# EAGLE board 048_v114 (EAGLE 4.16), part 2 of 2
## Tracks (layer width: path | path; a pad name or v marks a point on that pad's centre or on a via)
+3V3  (via drill 0.25)
  Top 0.15: IC3.10 7.28,33.38 7.28,33.78 IC3.11 7.48,34.18 v8.08,34.13 | v10.03,35.63 10.03,36.03 C4.1 9.68,37.08 9.43,37.63 6.38,37.63 6.03,37.93 6.03,38.68 4.08,40.48 | 4.08,40.48 4.08,38.48 R2.2 | 4.08,40.48 4.08,44.23 10.18,50.28 10.18,50.88 IC13.6 | T1.2 18.88,29.78 | 19.68,30.08 R18.2 20.33,30.18 20.38,30.08 | IC9.P$3 16.03,17.88 | 18.08,29.28 T1.2 | 26.98,37.28 IC8.6 27.98,36.98 | 26.98,38.08 IC8.5 | 33.08,37.08 IC8.3 35.28,36.88 35.28,36.68 | 27.88,29.48 27.88,29.38 IC7.8 | 27.88,30.18 IC7.7 28.93,30.58 | 35.08,31.48 C33.1 35.68,31.58 | 34.08,31.48 IC7.3 31.83,31.48 | v37.63,33.78 37.48,33.98 | T1.2 18.08,29.58 | IC14.36 54.88,10.83 54.88,11.88 55.23,12.13 63.03,12.13 63.38,11.68 IC12.1 63.88,10.58 64.23,10.23 65.03,10.23 65.28,10.58 IC12.3 65.78,11.68 v65.78,12.53 | 61.83,24.93 61.68,24.78 61.03,24.73 IC1.26 | 61.83,24.93 64.28,27.38 64.28,27.78 63.28,28.78 62.88,28.78 T2.2 62.08,29.48 61.78,29.48 60.78,30.48 v60.78,33.53 | 55.78,19.38 57.58,21.18 59.68,21.18 IC1.19 61.08,21.18 61.88,21.18 62.28,21.58 64.33,21.58 64.63,21.28 64.78,21.28 X7.1 | 55.78,19.38 55.33,18.98 55.28,18.73 IC1.10 | 55.78,19.38 52.28,22.93 50.43,22.93 49.78,23.63 49.38,23.63 IC1.57 48.03,23.58 v44.63,23.58 | v61.88,24.78 61.88,24.88 61.83,24.93 | v56.38,33.53 56.33,32.48 55.78,31.98 IC1.38 | C2.1 60.48,47.08 60.08,47.08 C25.1 59.18,47.58 58.58,47.58 | R9.2 53.88,48.88 53.48,48.88 51.88,47.53 51.88,46.58 IC6.32 51.88,45.68 51.83,44.38 54.88,41.28 | 58.58,47.58 55.98,47.58 54.68,48.88 R9.2 | 58.58,47.58 v58.58,46.93 | C1.2 58.68,36.88 59.18,36.88 C26.1 60.08,36.78 60.38,36.78 C27.1 | 54.88,41.28 55.48,41.88 56.68,41.88 IC6.19
  Top 0.15: 54.88,41.28 54.73,41.13 | 54.73,41.13 52.38,38.78 52.38,37.58 IC6.6 | 56.38,39.43 56.68,39.43 IC6.14 | 54.73,41.13 56.38,39.43 | 56.38,39.43 56.08,39.23 56.08,38.63 56.33,38.43 57.18,38.43 57.38,38.23 57.38,37.58 57.68,37.28 58.08,37.28 C1.2 | v58.48,35.88 58.48,36.48 C1.2 | IC6.45 48.58,40.38 48.73,40.48 48.98,40.68 48.98,41.18 48.68,41.38 IC6.43 47.68,41.43 46.28,41.43 45.88,41.78 45.83,43.03 45.88,43.73 46.18,43.93 47.68,43.93 IC6.38 | 39.08,47.68 IC10.3 | 38.98,49.28 IC10.1 | X3.5 46.38,53.38 46.93,52.68 48.93,52.68 49.18,52.43 51.58,52.43 52.53,53.38 X2.1 | 42.93,48.03 v43.13,48.28 | 53.88,49.48 R9.2
  Top 0.305: 18.88,29.78 19.48,29.88 19.68,30.08 | 16.03,17.88 17.63,19.48 17.63,28.93 18.08,29.28 | 26.98,37.28 26.98,38.08 | 32.58,36.98 27.98,36.98 | 33.08,37.08 32.58,36.98 | 27.88,30.18 27.88,29.48 20.98,29.48 20.78,29.58 20.38,30.08 | 34.08,31.48 35.08,31.48 | 35.68,31.58 v37.63,33.78 | 28.93,30.58 31.08,30.58 31.83,31.48 | 35.28,36.68 37.48,34.28 37.48,33.98 | 18.08,29.58 v16.53,29.58 | 39.58,48.28 39.08,47.68 | 39.58,48.28 39.53,48.98 38.98,49.28 | v43.13,48.28 39.58,48.28 | 45.83,43.03 36.53,43.03 36.48,43.18 | 36.48,43.18 36.13,43.58 36.13,44.18 36.53,44.58 39.73,44.58 42.93,48.03 | v52.88,50.48 53.88,49.48 | 32.58,36.98 32.58,38.98 v33.63,39.78 | v36.48,42.68 36.48,43.18
  Bottom 0.15: v10.03,35.63 8.98,34.13 v8.08,34.13 8.08,33.93 7.78,33.63 7.78,32.18 10.43,29.53 v16.53,29.58 | v37.63,33.78 41.28,33.78 U$1.31 | 42.78,23.68 42.78,25.58 42.28,25.88 U$1.15 | 42.78,23.68 42.78,22.58 42.38,22.38 42.28,22.38 U$1.8 | v44.63,23.58 42.78,23.68 | v61.88,24.78 64.98,21.68 X7.1 65.63,21.13 66.08,20.63 66.08,16.93 65.78,16.68 v65.78,12.53 | 58.93,35.43 59.08,35.58 C31.+ 60.78,34.78 v60.78,33.53 | 58.93,35.43 58.33,35.43 57.83,34.93 v56.38,33.53 | v58.58,46.93 59.08,47.08 C30.+ | v58.48,35.88 58.93,35.43 | 42.38,49.68 42.28,49.68 D1.A 42.28,48.08 | 52.28,51.08 53.08,51.88 53.08,53.28 X2.1
  Bottom 0.305: 42.38,49.68 43.03,50.48 51.53,50.48 52.28,51.08 v52.88,50.48 | v43.13,48.28 42.28,48.08 | v33.63,39.78 v36.48,42.68
+5V  (via drill 0.25)
  Top 0.15: 27.38,7.38 IC5.2 27.28,6.98 | 27.68,7.38 IC5.3 27.78,6.98 | 27.03,6.63 27.18,6.78 | 22.48,6.98 LED1.A 21.48,8.08 | v40.93,8.28 40.73,8.38 41.33,8.98 41.73,8.98 42.08,9.33 42.78,10.08 43.18,10.08 IC2.20 | 21.48,9.08 D4.A 20.38,9.08
  Top 0.305: 27.18,6.78 27.28,6.98 | 22.73,6.63 27.03,6.63 | 27.78,6.98 v27.73,6.08
  Top 0.406: 27.38,7.38 27.68,7.38 | 22.48,6.98 22.73,6.63 | 21.48,9.08 21.48,8.08 | v19.28,8.08 20.38,9.08
  Bottom 0.15: 14.28,8.08 L1.2 16.28,8.08 | v40.93,8.28 34.98,8.28 32.58,5.88 28.23,5.88 28.13,5.98 v27.73,6.08
  Bottom 0.305: 14.28,8.08 14.28,9.38 14,9.66 C36.1 13.94,10.29 14.88,11.23 14.84,11.28 C37.+
  Bottom 0.406: 16.28,8.08 v19.28,8.08
+BAT  (via drill 0.25)
  Top 0.15: R3.2 13.18,5.08 13.18,7.08 12.03,8.03 12.03,10.48 14.58,12.98 C17.2 15.28,13.88 | 15.28,16.08 IC9.P$4 | v31.43,46.88 31.48,47.38 IC11.2 | v32.13,51.83 32.38,51.43 | 32.48,51.18 32.48,50.98 IC11.7 | IC5.8 27.68,10.28 27.38,10.28 IC5.9 27.28,10.58 v27.28,11.18 | v7.08,18.18 3.48,21.78 IC4.14
  Top 0.305: 32.38,51.43 32.48,51.18
  Top 0.406: 15.28,13.88 v15.28,15.03 15.28,16.08
  Bottom 0.15: 29.98,8.08 C9.+ | 17.13,3.93 R13.1 | v7.08,18.18 11.78,18.18 11.83,18.03 11.88,18.08 | 31.28,46.78 v31.43,46.88 | v15.28,15.03 15.18,14.78 15.13,14.98
  Bottom 0.305: v31.43,46.88 31.48,50.78 v32.13,51.83 | v27.28,11.18 27.28,10.78 29.38,8.68 | 29.38,8.68 29.98,8.08 | 20.23,3.93 22.18,3.93 22.58,3.38 23.98,3.38 29.38,8.68 | 20.23,3.93 17.13,3.93 | 11.83,18.03 15.13,14.98 19.43,14.98 20.23,14.18 20.23,3.93 | 31.28,46.78 30.93,46.78 30.18,45.78 29.83,45.78 29.58,46.03 27.93,46.03 17.18,35.28 17.18,28.88 11.88,23.68 11.88,18.08
AGND  (via drill 0.25)
  Top 0.15: C2.2 60.48,48.78 60.08,48.78 C25.2 59.18,49.28 v58.63,49.88 | C24.1 40.78,40.68 40.78,39.58 R12.2 | 48.98,42.18 48.73,42.43 IC6.41 48.18,42.48 48.18,42.88 IC6.40 | 48.98,42.18 49.38,41.83 49.38,39.78 48.83,39.38 48.58,39.38 IC6.47 47.68,39.38 46.13,39.38 45.63,39.98 41.93,39.98 41.23,40.68 41.28,40.68 C24.1 | 48.98,42.18 49.08,42.28 49.08,44.18 48.68,44.38 48.58,44.38 IC6.37 48.58,44.48 v48.58,44.98 | 9.48,51.58 IC13.5 9.28,50.88 9.28,50.08 3.38,44.18 3.38,43.48 R25**.2 | 9.48,53.28 IC13.2 9.48,54.08 10.03,54.53 14.13,54.53 16.98,51.38 16.98,49.93 16.83,49.78 16.83,48.18 C44.1 16.38,47.28 16.38,46.48 C40.1 16.38,45.58 16.38,44.68 C41.1 | v55.73,20.33 56.18,20.48 56.33,20.63 57.28,21.63 59.73,21.63 IC1.20 | v35.28,7.08 35.28,8.38 34.03,9.48 34.03,11.38 32.28,12.88 31.28,13.83 v27.78,13.83 | v18.18,34.58 15.98,36.78 15.98,38.03 15.58,38.38 C23.1 15.58,39.28 15.58,39.48 15.93,39.73 15.93,41.43 15.58,41.78 C22.2 14.68,42.58 15.88,43.78 C41.1 | C24.1 40.28,40.98 19.68,40.98 16.88,43.78 C41.1
  Top 0.305: 9.48,53.28 9.48,51.58
  Bottom 0.15: C30.- 59.08,49.88 v58.63,49.88 58.38,49.78 57.33,49.78 54.23,46.18 49.83,46.18 v48.58,44.98 | v55.73,20.33 55.73,20.18 52.28,16.73 52.28,11.88 50.83,10.43 46.83,10.43 43.48,7.08 v35.28,7.08 | v27.78,13.83 24.93,17.28 23.13,17.28 22.13,18.48 22.13,24.13 23.33,25.08 25.13,25.08 25.63,25.53 25.63,26.53 24.63,27.53 22.33,27.53 21.08,28.73 19.08,28.73 18.18,29.58 v18.18,34.58
BT_RES  (via drill 0.25)
  Top 0.15: v51.73,6.03 53.38,6.03 IC14.43 | v57.38,16.88 IC1.14
  Bottom 0.15: v51.73,6.03 52.08,6.38 52.08,8.63 54.73,11.23 54.73,15.78 55.78,16.88 v57.38,16.88
BUSA0  (via drill 0.25)
  Top 0.15: v34.33,16.93 35.88,15.48 IC2.1 | v50.88,28.33 51.33,28.33 51.78,28.98 IC1.46
  Bottom 0.15: v34.33,16.93 34.33,20.73 U$3.1 33.33,22.58 33.33,24.03 39.08,29.78 41.28,29.78 U$1.23 42.28,29.88 42.43,29.78 48.53,29.78 49.98,28.33 v50.88,28.33
BUSA1  (via drill 0.25)
  Top 0.15: v46.53,27.93 47.88,27.93 IC1.49 | v34.78,12.78 35.88,12.78 IC2.5 | v30.08,20.08 v34.13,23.83
  Bottom 0.15: v46.53,27.93 45.38,29.28 42.28,29.28 U$1.22 41.28,29.28 39.28,29.28 34.13,24.13 v34.13,23.83 | 28.88,18.93 27.33,20.58 U$3.3 | 28.88,18.93 32.28,15.13 32.73,14.68 32.73,13.98 33.93,12.78 v34.78,12.78 | 28.88,18.93 v30.08,20.08
BUSA2  (via drill 0.25)
  Top 0.15: v44.88,28.63 46.28,27.23 48.03,27.23 IC1.50 | v34.78,15.23 35.53,14.08 IC2.3
  Bottom 0.15: v44.88,28.63 44.63,28.63 44.48,28.78 42.28,28.78 U$1.21 41.28,28.78 39.63,28.78 34.98,24.18 34.98,15.33 | 34.98,15.33 v34.78,15.23 | 34.98,15.33 32.73,17.53 32.73,28.68 31.53,30.13 31.53,31.23 U$3.5
BUSA3  (via drill 0.25)
  Top 0.15: v45.03,27.58 45.23,27.38 45.98,26.78 47.53,26.78 47.58,26.73 47.98,26.73 IC1.51 | v35.18,9.58 35.78,8.98 35.88,8.98 IC2.11
  Bottom 0.15: v45.03,27.58 44.33,28.28 42.28,28.28 U$1.20 41.28,28.28 39.93,28.28 37.48,25.93 35.43,23.88 35.43,13.88 35.13,13.43 | v35.18,9.58 35.18,11.78 35.38,11.98 35.38,13.08 35.13,13.43 | 35.13,13.43 34.63,13.43 34.38,13.68 30.68,17.68 30.68,20.68 U$3.2
BUSA4  (via drill 0.25)
  Top 0.15: v47.08,26.23 47.88,26.18 IC1.52 | v37.58,16.93 37.58,15.08 37.43,14.78 37.23,14.78 IC2.2 | v39.48,26.78 v37.23,28.98
  Bottom 0.15: v47.08,26.23 45.43,26.23 44.58,27.08 43.93,27.78 42.28,27.78 U$1.19 41.28,27.78 40.58,27.78 39.58,26.88 | v37.58,16.93 37.58,18.03 36.78,18.83 36.78,22.68 39.23,25.08 39.23,26.48 39.58,26.88 | v37.23,28.98 34.38,31.88 U$3.6 | 39.58,26.88 v39.48,26.78
BUSA5  (via drill 0.25)
  Top 0.15: v43.83,26.88 44.68,26.03 46.28,26.03 46.63,25.68 48.08,25.68 IC1.53 | v37.78,10.18 37.18,10.18 IC2.9 | v38.48,25.98 39.53,25.98 v39.98,26.08
  Bottom 0.15: v43.83,26.88 43.33,27.18 43.23,27.28 42.28,27.28 U$1.18 41.28,27.28 41.08,27.28 v39.98,26.08 | v37.78,10.18 37.78,10.58 35.88,12.48 35.88,23.58 38.28,25.98 v38.48,25.98
BUSA6  (via drill 0.25)
  Top 0.15: v46.13,25.33 46.38,25.33 46.53,25.18 48.08,25.18 IC1.54 | v39.68,11.28 38.43,9.48 37.23,9.48 IC2.10
  Bottom 0.15: U$1.17 42.28,26.78 43.03,26.78 44.48,25.33 v46.13,25.33 46.48,24.18 44.48,22.08 44.48,17.58 39.68,12.78 v39.68,11.28
BUSA7  (via drill 0.25)
  Top 0.15: v45.38,24.68 48.08,24.68 IC1.55 | v39.18,16.93 39.18,13.13 38.28,12.28 37.18,12.28 IC2.6
  Bottom 0.15: v45.38,24.68 44.38,24.68 42.78,26.28 42.28,26.28 U$1.16 41.28,26.28 41.08,26.28 37.18,22.38 37.18,19.43 39.18,17.43 v39.18,16.93
EN_LOAD  (via drill 0.25)
  Top 0.15: v26.68,11.83 26.68,10.58 IC5.10 | v32.08,8.68 32.48,8.58 33.03,8.58 34.03,7.48 34.08,7.43 34.08,6.13 34.63,5.58 37.38,5.58 v37.73,5.78 | v53.73,15.38 53.73,16.53 54.28,17.08 IC1.8
  Bottom 0.15: v26.68,11.83 27.53,11.83 27.98,11.33 27.98,10.78 30.13,8.63 31.73,8.63 31.78,8.68 v32.08,8.68 | v37.73,5.78 43.68,5.78 45.68,7.78 50.03,7.78 53.73,11.48 v53.73,15.38
EN_REG  (via drill 0.25)
  Top 0.15: R19.1 26.38,4.68 24.98,4.68 D3.C 23.68,4.73 22.43,4.73 21.93,3.98 20.08,3.98 15.93,8.18 15.93,10.23 17.03,11.28 23.78,11.28 | v16.83,20.58 15.98,20.58 IC9.P$1 | 23.78,11.28 23.78,10.78 D4.C | 23.78,11.28 v23.78,13.83
  Bottom 0.15: v23.78,13.83 v16.83,20.58
ENTPS  (via drill 0.25)
  Top 0.15: v33.78,51.58 33.08,50.98 IC11.6 | v36.63,51.58 37.13,51.58 38.58,50.13 42.03,50.13 42.23,49.88 v43.38,49.78 | v48.48,32.93 50.23,31.23 50.23,29.13 50.28,29.08 50.28,28.03 50.63,27.68 51.48,27.68 52.18,28.58 52.28,28.98 IC1.45
  Bottom 0.15: v36.63,51.58 v33.78,51.58 | v43.38,49.78 43.58,49.78 43.68,49.88 44.53,49.88 44.78,49.68 44.78,42.38 44.58,42.18 44.58,36.48 45.38,35.73 45.73,35.73 46.08,35.38 46.08,33.83 46.98,32.93 v48.48,32.93
FLASH  (via drill 0.25)
  Top 0.15: v55.38,13.43 54.63,13.43 54.08,13.03 v50.68,13.03 | v47.53,13.28 47.28,13.28 43.58,16.98 v41.48,16.98 | v39.73,19.83 39.48,19.93 38.73,20.53 38.73,23.93 40.58,25.78 40.58,32.68 35.18,38.08 IC8.4 | v55.78,15.13 IC1.11
  Bottom 0.15: v55.78,15.13 55.78,13.98 v55.38,13.43 | v50.68,13.03 48.13,13.03 v47.53,13.28 | v39.73,19.83 v41.48,16.98
FRAM  (via drill 0.25)
  Top 0.15: v57.43,20.13 57.73,20.13 57.93,19.93 59.58,19.93 59.68,20.03 59.68,20.08 IC1.17 | v34.73,6.43 34.73,6.63 34.58,6.78 34.58,7.73 33.48,8.83 33.48,10.93 32.78,11.58 32.63,11.68 30.18,11.68 v29.98,11.93 | v30.23,16.58 v31.28,18.03 | v31.28,23.88 31.28,28.13 31.98,28.88 IC7.1
  Bottom 0.15: v57.43,20.13 53.13,15.88 53.13,11.53 50.03,8.43 45.58,8.43 43.58,6.43 v34.73,6.43 | v29.98,11.93 29.98,13.58 30.23,13.83 v30.23,16.58 | v31.28,18.03 v31.28,23.88
FTPWEN  (via drill 0.25)
  Top 0.15: v40.68,10.58 38.38,8.28 36.98,8.28 IC2.12 | v46.98,21.53 47.28,21.53 47.68,21.68 IC1.61
  Bottom 0.15: v40.68,10.58 46.13,15.98 46.48,15.98 46.98,16.48 v46.98,21.53
FTRD  (via drill 0.25)
  Top 0.15: v41.83,10.83 38.68,7.68 37.18,7.68 IC2.13 | v47.28,22.73 47.68,23.13 IC1.58
  Bottom 0.15: v41.83,10.83 47.83,16.58 47.83,22.03 47.48,22.38 v47.28,22.73
FTRXF
  Top 0.15: IC2.23 44.48,12.28 47.48,12.28 49.03,13.83 49.08,13.93 49.08,15.03 49.58,15.68 50.08,15.68 50.53,16.08 51.28,16.93 IC1.2
FTTXE
  Top 0.15: IC2.22 44.48,11.58 47.38,11.58 49.53,13.73 49.53,14.73 49.93,15.18 50.33,15.18 51.28,16.13 51.78,16.68 IC1.3
FTWR  (via drill 0.25)
  Top 0.15: v41.58,9.68 41.38,9.68 38.78,7.08 37.18,7.08 IC2.14 | v50.03,22.18 49.48,22.68 IC1.59
  Bottom 0.15: v41.58,9.68 41.98,10.03 42.33,10.33 42.43,10.33 49.48,17.38 49.48,21.68 v50.03,22.18
GND  (via drill 0.25)
  Top 0.15: C1.1 58.68,38.18 59.18,38.18 C26.2 | 58.68,39.38 59.18,38.88 C26.2 | 58.68,39.38 57.68,40.38 57.58,40.38 IC6.16 | C26.2 60.08,38.48 60.38,38.48 C27.2 60.88,38.98 60.88,40.68 C28.1 | v58.48,39.18 58.68,39.38 | C12.1 65.18,46.78 65.18,46.28 C13.1 64.88,45.48 64.08,45.48 62.33,43.73 61.53,43.73 60.98,43.18 C3.1 60.48,42.28 60.48,41.58 C28.1 | IC6.20 57.18,42.48 57.18,42.88 IC6.21 | IC6.22 57.18,43.38 57.18,42.98 IC6.21 | IC6.21 57.58,42.88 58.78,42.88 60.08,41.58 C28.1 | C11.1 65.58,35.48 C10.1 65.28,34.18 63.98,34.18 63.08,33.28 63.08,32.38 64.68,30.78 65.08,30.78 66.13,29.93 66.13,26.48 65.48,25.93 X1.3 64.78,25.48 63.58,24.28 61.13,24.23 IC1.25 | C8.1 54.78,14.68 IC1.9 | C45.2 64.38,14.88 64.38,11.68 IC12.2 | X7.3 64.93,18.53 64.33,18.18 64.33,15.68 C45.2 | C8.1 55.38,14.38 62.98,14.38 63.68,15.08 C45.2 | C35.2 33.98,14.13 34.03,12.43 35.03,11.38 35.88,11.58 IC2.7 37.18,11.48 v37.98,11.58 38.98,11.63 39.23,12.08 42.68,12.08 | IC2.26 43.88,13.98 43.88,13.58 IC2.25 43.18,13.28 43.08,13.28 42.63,13.03 42.68,12.08 | C34.1 45.58,8.98 44.48,8.98 IC2.18 | C34.1 46.08,9.28 44.68,10.68 44.48,10.68 IC2.21 43.18,10.88 42.68,11.13 42.68,12.08 | Q4.P$4 46.78,3.18 45.98,2.38 C47.2 45.38,2.18 v44.68,2.18 | Q4.P$4 48.08,3.28 50.38,0.98 Q4.P$2 51.88,0.68 52.48,0.68 C46.2 52.98,0.33 54.08,0.33 54.98,1.63 IC14.1 55.08,3.18 55.33,3.73 55.38,3.78 IC14.49 59.08,3.78 59.08,3.18 IC14.9 | IC14.9 59.08,2.38 59.48,2.38 IC14.10 | IC14.3 56.08,2.38 56.48,2.38 IC14.4 56.58,2.38 56.98,2.38 IC14.5 57.08,2.38 57.48,2.38 IC14.6 57.58,2.38 57.98,2.38 IC14.7 58.08,2.38 58.48,2.38 IC14.8 58.58,2.38 58.98,2.38 IC14.9
  Top 0.15: C34.1 46.18,8.48 46.28,8.48 46.58,8.18 46.58,3.88 Q4.P$4 | C8.1 54.58,14.08 54.08,13.58 50.18,13.58 46.18,9.28 C34.1 | -BAT.1 9.18,2.98 9.18,4.48 R7.1 9.53,5.08 9.53,9.48 8.88,10.03 U$2.P$5 8.58,10.98 8.58,15.58 IC4.5 8.58,17.58 10.58,19.58 | C14.1 12.18,32.48 11.68,32.48 C15.1 11.03,32.63 11.03,34.98 | 11.03,34.98 11.03,37.58 10.58,37.78 C4.2 | C39.2 1.18,21.88 L5.2 1.78,26.08 3.93,23.93 | 3.93,23.93 4.18,23.68 IC4.13 | 5.53,24.28 4.28,24.28 3.93,23.93 | 5.53,24.28 6.63,24.28 6.83,23.68 6.78,23.68 IC4.11 7.28,21.78 7.63,21.23 8.83,21.23 9.28,21.78 IC4.9 9.88,21.78 10.58,21.08 10.58,19.58 | 10.58,19.58 10.58,17.58 IC4.7 | 5.53,24.28 5.48,30.88 IC3.3 5.48,31.38 5.48,31.78 IC3.21 6.48,33.38 6.48,33.68 IC3.12 6.53,34.53 7.33,35.33 8.13,35.33 8.48,35.68 9.03,35.68 9.63,34.98 11.03,34.98 | IC10.2 37.88,48.78 36.98,48.78 C48.2 36.38,49.38 34.98,50.78 R29.1 | IC11.P$1 32.48,48.68 32.48,48.08 IC11.4 32.48,47.38 33.48,46.38 33.48,46.08 C50.1 | IC11.8 31.98,50.28 31.98,49.78 IC11.P$1 | R29.1 34.38,50.48 33.68,49.78 IC11.P$1 | R29.1 35.18,51.28 35.98,52.18 41.93,52.13 43.18,53.38 X3.3 43.73,53.98 44.13,54.53 50.38,54.53 50.68,54.38 50.68,53.53 50.93,53.28 v51.33,53.08 | 53.13,51.53 51.08,49.48 R8.2 50.38,48.88 50.38,46.58 IC6.35 50.38,45.68 50.38,44.53 50.83,44.08 50.83,42.68 51.28,42.23 51.28,38.58 50.98,38.18 | 53.13,51.53 54.98,53.38 X2.3 | 50.98,38.18 42.88,38.18 R12.1 42.08,38.18 42.08,36.68 42.83,36.13 v42.83,35.23 | 50.98,38.18 51.38,37.78 51.38,37.58 IC6.4 51.38,36.33 50.93,35.88 50.93,34.43 R5.2 51.28,34.38 54.28,31.08 IC1.41 | 53.13,51.53 v52.38,52.13
  Top 0.15: 25.88,31.08 25.23,31.78 25.23,34.93 25.88,35.43 25.88,35.48 IC8.7 | 25.88,31.08 30.38,31.08 31.98,32.68 IC7.4 34.08,32.78 35.08,32.78 C33.2 35.68,32.78 v36.18,33.28 | IC5.4 28.28,6.98 28.28,4.98 R19.2 28.48,4.53 30.23,4.53 30.63,5.18 30.48,7.28 C16.2 31.38,7.28 32.78,7.28 v32.98,7.43 | v20.03,29.43 20.03,28.98 C32.2 | v28.28,12.08 28.28,10.58 IC5.7 | v22.78,19.58 22.18,19.58 IC9.P$5 20.78,17.38 17.28,13.88 C17.1 16.68,12.98 v16.68,12.43 | v25.58,30.23 25.88,31.08
  Bottom 0.15: v58.48,39.18 59.08,39.18 C31.- 61.43,38.68 64.58,38.68 65.08,38.18 64.98,29.48 63.18,28.08 | 62.93,27.88 63.18,28.08 | 62.93,27.88 62.93,27.48 64.53,25.88 X1.3 | v44.68,2.18 44.68,1.68 ANT2.P$3 | 62.93,27.88 62.83,27.88 62.03,28.83 61.38,28.83 60.93,28.33 60.98,24.68 64.43,21.08 64.43,19.33 64.93,19.03 X7.3 | 62.93,27.88 63.13,27.93 63.18,28.08 | C43.- 35.98,50.98 36.88,50.98 40.33,54.53 42.73,54.53 43.28,53.98 X3.3 | 42.53,34.23 42.28,34.38 U$1.32 | 42.53,34.23 42.68,34.08 42.68,33.58 42.38,33.38 42.28,33.38 U$1.30 41.28,33.28 38.73,33.28 38.58,33.08 37.08,33.08 36.98,33.28 v36.18,33.28 | 42.43,35.23 42.73,35.08 42.73,34.18 42.53,34.23 | 42.43,35.23 42.38,35.28 42.28,35.28 U$1.34 | 42.43,35.23 v42.83,35.23 | v52.38,52.13 v51.33,53.08 | U$1.10 41.78,23.38 41.78,23.78 U$1.11 41.78,23.88 41.78,24.28 U$1.12 41.78,24.38 41.78,24.78 U$1.13 41.28,24.88 41.08,25.08 | 42.43,19.43 42.73,19.58 42.73,20.08 42.28,20.38 U$1.4 41.28,20.38 40.78,20.38 39.98,21.18 39.98,23.88 39.93,23.93 | 42.43,19.43 42.38,19.38 42.28,19.38 U$1.2 | 41.08,25.08 41.28,25.28 U$1.14 | 39.93,23.93 41.08,25.08 | 39.93,23.93 38.08,22.08 38.08,21.98 R17.1 | v20.03,29.43 21.33,29.48 22.28,28.18 23.33,28.18 U$4.P$6 | U$4.P$9 24.98,20.48 28.58,16.88 28.58,11.83 v28.28,12.08 29.93,10.18 C9.- 32.38,9.28 32.83,8.83 | U$4.P$6 24.98,28.08 24.98,28.13 26.13,27.03 26.13,25.38 24.98,24.33 23.23,24.33 22.88,23.98 22.88,21.68 23.38,21.28 U$4.P$9 | v32.98,7.43 32.98,8.83 32.83,8.83 | 42.43,19.43 42.58,19.53 42.58,19.33 42.98,18.98 43.03,16.93 40.13,14.03 38.33,14.03 37.98,13.63 v37.98,11.58 38.38,10.83 38.48,10.73 38.48,9.83 37.18,8.88 32.88,8.88 32.83,8.83
  Bottom 0.15: v22.78,19.58 23.68,20.48 U$4.P$9 | v25.58,30.23 25.08,29.58 U$4.P$6 | v16.68,12.43 16.63,13.03
  Bottom 0.305: 12.64,10.52 C36.2 | 12.64,10.52 11.78,11.38 11.79,11.38 C37.- 11.32,11.57 10.28,10.53 8.73,10.53 8.68,10.58 U$2.P$5 | 12.64,10.52 12.64,13.09 13.08,13.53 16.33,13.53 16.73,13.13 16.73,12.58 16.78,12.53 v16.68,12.43
  pour Bottom (isolate 0.406): 0.18,54.68 66.23,54.68 66.23,0.23 0.28,0.23 0.28,54.63
  pour Top (isolate 0.406): 0.23,54.68 66.23,54.68 66.23,0.18 0.33,0.18 0.33,54.68
INT1  (via drill 0.25)
  Top 0.15: 20.53,31.13 20.48,31.18 16.08,31.18 13.58,28.68 7.38,28.68 D2.A | 20.53,31.13 20.88,30.78 20.98,30.58 R18.1 | v53.23,31.23 53.78,30.58 IC1.42 | v49.48,31.08 47.48,33.08 47.48,34.23 47.13,34.58 45.93,34.58 45.78,34.48 41.98,34.48 v40.68,35.68 | v32.53,35.88 28.68,35.88 28.28,36.38 25.68,36.38 20.53,31.13
  Bottom 0.15: v49.48,31.08 52.98,31.08 53.13,31.23 v53.23,31.23 | v40.68,35.68 37.03,35.68 35.93,34.48 35.08,34.48 34.88,34.68 33.78,34.68 v32.53,35.88
JOY_COM  (via drill 0.25)
  Top 0.15: v52.53,31.93 52.53,30.93 52.78,30.73 IC1.44 | v48.13,35.73 47.88,35.73 47.63,35.98 44.13,35.98 v43.58,36.68
  Bottom 0.15: v52.53,31.93 52.53,35.43 51.98,35.98 50.83,35.98 50.58,35.73 v48.13,35.73 | v43.58,36.68 33.98,36.68 32.28,38.23 31.63,38.23 27.78,34.28 U$3.4
LEFT
  Top 0.15: 8.28,53.68 IC13.3
  Top 0.305: 8.28,53.68 6.48,53.68 X4.5
  Bottom 0.15: 6.83,51.53 6.88,51.58 | X6.1 6.88,41.98 | 5.88,52.58 X4.5
  Bottom 0.305: 6.88,41.98 6.83,51.53 | 6.83,51.53 5.88,52.58 | 6.83,51.53 11.53,51.53 12.03,51.03 14.43,51.03 15.13,51.58 18.63,51.58 19.48,50.83 20.48,50.78 C18.-
LOAD_PROG  (via drill 0.25)
  Top 0.15: v29.78,5.28 28.88,6.18 28.88,6.98 IC5.5 | v50.23,20.58 49.63,20.68 IC1.63
  Bottom 0.15: v29.78,5.28 32.63,5.28 35.03,7.68 43.38,7.68 46.58,10.93 46.43,13.43 50.23,17.23 v50.23,20.58
MCLR  (via drill 0.25)
  Top 0.15: v50.28,14.38 50.28,14.43 52.18,16.33 52.83,16.33 53.68,17.18 53.68,17.38 IC1.7 | v48.23,14.13 47.38,14.13 43.93,17.58 v42.33,17.58 | v36.83,23.63 36.83,27.23 v36.18,27.88 | v31.93,37.68 v30.58,39.48 | v30.58,41.68 30.58,44.33 28.78,46.28 28.78,52.63 30.68,54.48 40.08,54.48 40.58,53.98 X3.1
  Bottom 0.15: R1.1 40.28,50.88 40.28,52.78 40.78,53.28 X3.1 | v48.23,14.13 48.38,14.13 48.63,14.38 v50.28,14.38 | v42.33,17.58 42.33,16.88 41.78,16.33 37.18,16.33 36.33,17.23 36.33,23.13 v36.83,23.63 | v36.18,27.88 31.93,32.33 v31.93,37.68 | v30.58,39.48 v30.58,41.68
N$1  (via drill 0.25)
  Top 0.15: v55.48,39.28 55.48,37.88 55.38,37.78 55.38,37.58 IC6.12 | v57.98,48.48 57.98,50.23 61.28,53.38 X2.8
  Bottom 0.15: v55.48,39.28 55.48,45.83 v57.98,48.48
N$2  (via drill 0.25)
  Top 0.15: C10.2 65.28,33.08 64.68,33.08 Q1.2 | IC1.39 55.28,32.13 55.63,32.48 v55.63,32.93
  Bottom 0.15: v55.63,32.93 55.73,32.68 56.08,32.28 63.28,32.28 63.48,32.48 Q1.2
N$3
  Top 0.15: IC3.14 5.53,34.18 5.53,35.08 6.58,36.08 C6.1
N$4  (via drill 0.25)
  Top 0.15: v54.88,40.08 54.88,37.58 IC6.11 | v56.98,48.33 56.98,50.18 60.08,53.28 X2.7
  Bottom 0.15: v54.88,40.08 54.88,46.18 v56.98,48.33
N$5
  Top 0.15: IC3.13 6.03,34.18 6.03,34.83 7.08,35.83 7.88,35.83 8.18,36.08 C7.2
N$6
  Top 0.15: IC3.4 6.08,30.88 6.08,30.28 6.78,29.48 8.88,29.48 C5.2
N$7  (via drill 0.25)
  Top 0.15: v57.38,46.58 55.38,46.58 IC6.25
  Bottom 0.15: v57.38,46.58 58.83,48.28 61.58,48.33 62.03,48.73 62.03,51.78 61.53,52.28 59.63,52.28 59.13,52.78 59.13,52.93 X2.6
N$8  (via drill 0.25)
  Top 0.15: v12.78,8.58 15.98,11.73 20.38,11.73 22.98,14.38 32.18,14.38 C35.1
  Bottom 0.15: 12.28,8.08 L1.1 10.38,7.28 | U$2.P$1 9.08,7.28
  Bottom 0.406: 12.28,8.08 v12.78,8.58 | 9.08,7.28 10.38,7.28
N$9
  Top 0.15: IC3.19 4.08,32.28 3.33,32.18 2.88,32.38 2.88,35.78 3.48,36.38 R2.1
N$10
  Top 0.15: C5.1 9.08,27.38 9.08,26.58 L5.1
N$11
  Bottom 0.15: R1.2 38.58,50.28 38.58,49.68 D1.C
N$12  (via drill 0.25)
  Top 0.15: C11.2 65.28,37.38 64.68,37.38 Q1.1 | v55.73,34.13 55.03,33.53 55.03,32.48 54.78,32.23 IC1.40
  Bottom 0.15: v55.73,34.13 59.03,37.38 63.48,37.38 Q1.1
N$13  (via drill 0.25)
  Top 0.15: C34.2 45.58,7.98 44.58,7.98 44.48,8.08 IC2.17 43.18,8.28 v42.08,8.28 | v38.58,13.38 37.18,13.38 IC2.4
  Bottom 0.15: v38.58,13.38 38.58,11.38 v42.08,8.28
N$14  (via drill 0.25)
  Top 0.15: C12.2 64.88,48.58 64.68,48.58 Q2.2 64.08,48.08 63.08,47.08 R4.1 62.48,46.28 61.28,45.08 60.48,45.08 v58.53,43.53 | v58.53,42.28 57.68,41.48 57.58,41.48 IC6.18
  Bottom 0.15: v58.53,42.28 58.58,43.18 v58.53,43.53
N$15  (via drill 0.25)
  Top 0.15: R4.2 62.48,44.98 61.98,44.38 v61.13,44.38 60.58,44.38 v59.38,43.28 | C13.2 64.88,44.18 64.68,44.18 Q2.1 | v58.58,41.43 57.88,40.98 57.58,40.98 IC6.17
  Bottom 0.15: v61.13,44.38 63.68,44.38 Q2.1 | v58.58,41.43 59.38,41.93 v59.38,43.28
N$16
  Top 0.15: C39.1 1.18,19.18 1.18,18.58 R10.2 0.88,17.78 0.68,17.73 0.53,17.58 0.48,17.48 0.48,5.58 1.08,4.98 JP2.1 2.18,4.28 4.68,4.28 JP4.1
N$17  (via drill 0.25)
  Top 0.15: v42.78,37.28 49.78,37.28 IC6.1 | v36.88,37.28 33.93,40.53 17.28,40.53 C20.2 16.78,41.08 16.78,41.78 C22.1
  Bottom 0.15: v36.88,37.28 v42.78,37.28
N$18
  Top 0.15: IC3.17 4.08,33.38 3.88,33.38 3.68,33.58 3.68,35.08 4.98,36.38 R6.1
N$19
  Top 0.15: IC3.2 4.93,30.88 4.88,30.68 4.63,30.28 3.83,30.28 1.68,32.68 C38.1
N$20
  Top 0.15: C38.2 1.58,34.78 1.58,35.78 ANT1.1
N$21
  Top 0.15: IC5.1 26.68,7.38 24.58,7.38 LED1.C
N$22  (via drill 0.25)
  Top 0.15: v39.68,20.68 v40.58,21.38
  Bottom 0.15: v39.68,20.68 39.08,20.68 R16.1 | v40.58,21.38 41.28,21.38 U$1.6
N$23  (via drill 0.25)
  Top 0.15: 6.98,15.18 6.98,15.58 IC4.4 | 6.98,15.18 6.33,14.53 6.28,14.38 R11.1 | v18.68,10.13 18.08,9.43 18.08,7.58 19.48,6.18 20.28,6.18 D3.A | 6.98,15.18 v7.83,13.98
  Bottom 0.15: v18.68,10.13 18.68,12.93 17.38,14.18 9.93,14.18 9.73,13.98 v7.83,13.98
N$24  (via drill 0.25)
  Top 0.15: v8.63,33.38 8.28,32.88 8.18,32.78 7.38,32.78 IC3.9 | C14.2 13.48,32.08 13.48,31.58 Q3.1
  Bottom 0.15: v8.63,33.38 8.78,32.88 8.93,32.73 11.33,32.73 12.98,31.18 Q3.1
N$25  (via drill 0.25)
  Top 0.15: v5.93,36.83 5.88,37.28 5.48,37.68 R6.2 | v8.73,34.93 9.13,34.48 9.83,34.48 10.28,34.23 10.28,32.68 C15.2 9.98,32.08 10.48,31.58 Q3.2
  Bottom 0.15: v8.73,34.93 v5.93,36.83
N$26  (via drill 0.25)
  Top 0.15: v43.58,39.23 44.68,39.23 44.93,38.93 47.68,38.93 IC6.48 | v24.73,38.88 17.28,38.88 C23.2 16.78,38.38 16.78,37.78 C21.1
  Bottom 0.15: v43.58,39.23 31.33,39.23 30.98,38.88 v24.73,38.88
N$27  (via drill 0.25)
  Top 0.15: v51.63,14.83 53.13,14.83 C8.2 | v50.88,23.73 49.78,24.13 IC1.56
  Bottom 0.15: v51.63,14.83 51.63,22.48 50.93,23.18 v50.88,23.73
N$28
  Top 0.15: IC5.6 28.88,9.98 30.48,9.98 C16.1
N$29  (via drill 0.25)
  Top 0.15: IC6.10 54.28,37.18 53.88,37.18 IC6.9 53.88,37.63 53.88,38.98 53.78,39.08 v53.78,39.38 | R8.1 51.58,48.88 51.58,48.03 51.38,47.78 IC6.33 | IC6.34 50.88,46.18 51.28,46.18 IC6.33 | v52.73,41.58 51.68,42.68 51.28,43.08 51.28,43.98 51.38,44.08 51.38,45.68 IC6.33
  Bottom 0.15: v53.78,39.38 52.73,40.43 v52.73,41.58
N$30  (via drill 0.25)
  Top 0.15: v49.88,51.83 49.88,46.58 IC6.36 | v51.28,53.98 51.53,53.98 51.98,54.53 57.18,54.53 57.73,53.98 X2.5
  Bottom 0.15: v49.88,51.83 49.88,52.48 v51.28,53.98
N$31  (via drill 0.25)
  Top 0.15: v39.38,22.38 v40.58,22.38
  Bottom 0.15: v39.38,22.38 39.08,21.98 R16.2 | v40.58,22.38 41.08,21.88 41.28,21.88 U$1.7
N$32
  Top 0.15: IC6.44 47.68,40.93 44.78,40.93 44.63,41.23 42.93,41.23 C24.2
N$33  (via drill 0.25)
  Top 0.15: v38.98,19.18 40.78,19.18 41.78,20.18 41.78,20.58 42.08,20.88 v42.78,20.88
  Bottom 0.15: v38.98,19.18 38.08,19.78 38.08,19.88 R17.2 | v42.78,20.88 42.28,20.88 U$1.5
N$35
  Bottom 0.15: 15.48,1.18 R13.2
  Bottom 0.406: 15.48,1.18 14.28,1.18 +BAT.1
N$36  (via drill 0.25)
  Top 0.15: v16.93,27.58 16.78,28.28 T1.1 | v20.98,27.78 20.98,28.38 C32.1
  Bottom 0.15: 20.83,27.68 21.08,27.78 22.48,26.38 23.38,26.38 U$4.P$7 | v16.93,27.58 17.23,27.58 17.33,27.68 20.83,27.68 | 20.83,27.68 v20.98,27.78
N$37
  Top 0.15: R10.1 1.38,16.48 1.43,16.48 2.58,15.08 3.83,15.08 4.18,15.58 IC4.2 4.78,16.58 5.48,16.58 IC4.3
N$38
  Top 0.15: IC4.1 3.48,17.58 3.73,18.13 6.13,18.13 6.38,17.68 6.38,15.33 5.78,14.88 5.38,14.88 4.88,14.38 R11.2 4.98,13.88 4.98,6.78 6.78,5.28 6.78,2.98 5.68,2.18 JP3.1 4.68,1.48 2.18,1.48 JP1.1
N$39
  Top 0.15: T1.3 18.88,27.28 19.58,27.28 19.68,27.18 R15.1
N$40  (via drill 0.25)
  Top 0.15: v35.78,2.78 39.38,2.78 41.08,4.43 42.48,5.83 44.23,5.83 44.88,6.48 44.88,7.18 44.58,7.48 44.48,7.48 IC2.16
  Bottom 0.15: v35.78,2.78 19.78,2.78 19.18,3.38 17.88,3.38 17.33,2.78 15.08,2.78 11.83,6.03 10.13,6.03 9.88,6.33 7.93,6.33 7.48,6.93 7.48,7.63 U$2.P$2
N$41  (via drill 0.25)
  Top 0.15: v14.93,2.08 16.58,0.38 32.88,0.38 35.68,4.58 35.88,4.78 37.93,4.78 39.28,6.13 39.88,6.78 43.18,6.78 IC2.15
  Bottom 0.15: v14.93,2.08 12.98,4.08 6.98,4.08 6.48,4.38 6.48,8.38 6.83,8.88 8.08,8.88 U$2.P$3
N$42
  Top 0.15: R25**.1 0.88,43.48 | 0.88,45.08 R22**.1 1.43,46.43
  Top 0.305: 0.88,43.48 0.88,45.08 | 1.43,46.43 1.43,48.13 X4.1
N$43
  Top 0.15: C48.1 36.98,47.28 37.08,47.28 37.38,46.98 40.08,46.98 40.48,47.38 IC10.4
N$44
  Top 0.15: IC14.14 62.18,4.03 63.48,4.03 64.48,5.03 64.48,7.58 64.98,8.08 X8.4
N$45
  Top 0.15: R14.1 19.18,45.98 18.58,45.98 C40.2
N$46
  Top 0.15: R20.1 19.18,44.28 18.58,44.28 C41.2
N$47  (via drill 0.25)
  Top 0.15: v29.98,48.13 30.88,47.98 IC11.1
  Bottom 0.15: v29.98,48.13 29.48,48.03 L4.1
N$48
  Top 0.15: R23.1 23.18,44.48 22.48,45.18 17.48,45.18 17.28,45.38 17.28,49.48 17.68,49.88 C19.+
N$49
  Top 0.15: R24.1 23.38,46.28 23.38,49.88 C18.+
N$50  (via drill 0.25)
  Top 0.15: v30.48,51.43 30.88,50.98 IC11.10
  Bottom 0.15: v30.48,51.43 29.48,52.98 L4.2
N$51
  Top 0.15: C45.1 65.38,14.88 65.38,14.28 IC12.4
N$52
  Top 0.15: R21.1 19.08,47.78 18.58,47.78 C44.2
N$53
  Top 0.15: IC11.3 31.98,47.38 31.98,46.08 C50.2
N$54  (via drill 0.25)
  Top 0.15: v62.98,8.33 62.63,8.33 62.28,7.98 IC14.22
  Bottom 0.15: v62.98,8.33 63.83,8.33 64.83,9.33 65.68,9.33 66.08,8.88 66.08,5.18 65.68,4.83 X8.1
N$55
  Top 0.15: IC11.5 33.08,47.53 34.38,47.53 R27.2
N$56  (via drill 0.25)
  Top 0.15: R28.1 32.78,52.98 32.78,53.48 C51.2 | v33.78,48.08 34.08,48.38 34.08,48.68 34.38,48.98 R27.1 | v32.98,51.93 32.98,52.38 R28.1 | R29.2 34.38,52.38 33.18,52.38 R28.1
  Bottom 0.15: v33.78,48.08 32.98,49.08 v32.98,51.93
N$57  (via drill 0.25)
  Top 0.15: v61.88,2.83 60.58,2.83 IC14.12
  Bottom 0.15: v61.88,2.83 64.78,5.78 X8.2
N$58  (via drill 0.25)
  Top 0.15: v63.48,7.53 63.13,7.68 62.58,7.68 62.38,7.53 62.13,7.53 IC14.21
  Bottom 0.15: v63.48,7.53 64.88,7.48 X8.3
N$60  (via drill 0.25)
  Top 0.15: v55.33,0.98 55.48,1.38 55.48,1.58 IC14.2
  Bottom 0.15: v55.33,0.98 54.58,0.98 54.28,1.28 54.28,1.43 54.08,1.58 51.88,1.58 50.43,3.18 44.73,3.18 ANT2.P$2
N$61  (via drill 0.25)
  Top 0.15: Q4.P$3 51.68,3.18 52.48,2.38 C46.1 52.98,2.18 v53.78,2.18 | v62.83,6.98 62.18,6.98 IC14.20
  Bottom 0.15: v62.83,6.98 58.53,6.98 v53.78,2.18
N$62  (via drill 0.25)
  Top 0.15: C47.1 45.98,0.68 46.58,0.68 Q4.P$1 48.13,0.78 v48.73,0.78 | v63.48,6.28 62.58,6.28 62.38,6.48 62.18,6.48 IC14.19
  Bottom 0.15: v63.48,6.28 61.53,6.28 55.58,0.33 49.23,0.33 49.08,0.48 v48.73,0.78
N$63  (via drill 0.25)
  Top 0.15: v61.43,30.73 62.08,30.73 T2.3 | v61.78,19.63 61.73,18.98 R22.1
  Bottom 0.15: v61.43,30.73 57.88,27.28 57.88,26.18 61.78,22.28 v61.78,19.63
N$64
  Top 0.15: R22.2 59.58,18.68 58.38,18.68 IC1.16
N$65
  Top 0.15: T2.1 64.98,29.78 64.98,28.58 X1.1
OLEDCSB  (via drill 0.25)
  Top 0.15: v42.78,31.38 42.78,31.18 42.28,30.93 42.28,25.03 45.08,22.18 48.08,22.18 IC1.60
  Bottom 0.15: v42.78,31.38 42.28,31.38 U$1.26
OLEDRDB  (via drill 0.25)
  Top 0.15: v45.68,31.73 46.48,31.73 49.88,28.38 49.88,27.58 50.78,27.08 53.23,27.08 54.78,25.38 v54.83,25.18 | v58.03,25.18 59.68,25.18 IC1.27
  Bottom 0.15: v45.68,31.73 45.18,31.73 45.03,31.88 45.03,31.93 42.23,31.93 U$1.27 | v54.83,25.18 v58.03,25.18
OLEDRESETB  (via drill 0.25)
  Top 0.15: v43.03,32.98 43.13,32.88 43.43,32.53 43.43,31.13 42.78,30.58 42.78,26.28 45.08,24.03 46.73,24.03 46.83,24.13 v47.33,24.13 | v48.88,18.63 50.68,18.63 IC1.1
  Bottom 0.15: v43.03,32.98 42.68,32.88 | 42.68,32.88 42.88,32.88 | 42.68,32.88 42.28,32.88 U$1.29 | v47.33,24.13 47.28,23.58 48.88,21.93 v48.88,18.63
OLEDRS  (via drill 0.25)
  Top 0.15: v45.53,30.88 v47.68,28.73 | v51.38,24.48 v55.53,24.48 | v58.88,24.13 59.48,23.68 IC1.24
  Bottom 0.15: v45.53,30.88 45.18,30.88 45.18,30.93 43.28,30.93 43.08,30.78 42.28,30.78 U$1.25 | v47.68,28.73 49.63,26.73 49.73,26.63 49.73,26.18 49.98,25.98 50.28,25.98 50.43,25.88 50.63,25.68 51.38,24.73 v51.38,24.48 | v55.53,24.48 58.63,24.48 v58.88,24.13
OLEDWRB  (via drill 0.25)
  Top 0.15: v46.58,30.68 v48.68,28.63 | v50.33,26.53 52.98,26.53 v52.98,26.48 | v54.68,27.08 55.33,27.08 56.78,25.73 59.33,25.73 IC1.28
  Bottom 0.15: v46.58,30.68 46.53,31.93 46.08,32.38 42.28,32.38 U$1.28 | v48.68,28.63 49.98,27.48 50.28,27.18 v50.33,26.53 | v52.98,26.48 54.03,26.48 v54.68,27.08
PGC  (via drill 0.25)
  Top 0.15: v45.38,35.08 47.18,35.08 50.78,31.48 IC1.48 | v44.18,49.28 44.18,53.13 X3.4
  Bottom 0.15: v45.38,35.08 44.18,36.28 v44.18,49.28
PGD  (via drill 0.25)
  Top 0.15: v46.93,36.73 48.23,36.73 48.73,36.18 48.73,34.18 51.28,31.63 IC1.47 | v46.78,48.63 46.78,49.48 v44.88,51.48
  Bottom 0.15: v46.93,36.73 46.93,41.53 47.13,41.78 47.13,48.38 v46.78,48.63 | v44.88,51.48 43.83,51.48 42.18,53.28 X3.2
RIGHT
  Top 0.15: 12.83,50.83 12.78,50.63 13.08,50.78
  Top 0.305: 12.78,50.63 10.43,52.98 IC13.1 | 12.83,50.83 15.38,50.78 C19.- | X5.1 11.28,41.98 10.48,42.78 X4.2 10.48,44.88 13.08,47.48 13.08,50.78
SCK2  (via drill 0.25)
  Top 0.15: 26.33,31.78 25.63,32.38 25.63,33.28 26.03,33.63 31.08,33.63 33.08,35.48 IC8.2 | 26.33,31.78 26.38,31.88 26.78,31.88 IC7.6 | v28.73,18.18 29.58,18.18 30.13,18.78 37.23,18.78 38.08,18.08 41.03,18.08 42.18,19.23 51.98,19.23 52.23,18.98 52.23,18.78 IC1.4 | v26.28,31.68 26.28,31.88 26.33,31.78
  Bottom 0.15: v28.73,18.18 28.58,18.38 26.18,20.78 26.18,22.68 25.13,23.58 | 25.13,23.58 24.98,23.88 U$4.P$8 | v26.28,31.68 26.28,27.73 26.98,27.03 27.03,25.28 25.13,23.58
SCL1  (via drill 0.25)
  Top 0.15: v9.08,31.78 7.38,31.78 IC3.7 | v12.03,30.88 12.08,30.48 12.63,29.88 13.73,29.88 14.13,30.18 17.18,33.18 18.93,33.18 19.38,33.63 19.38,35.98 21.63,38.23 24.88,38.23 26.83,40.08 31.83,40.08 31.98,39.88 v32.68,39.88 | v36.93,43.83 41.58,43.83 45.78,47.98 47.18,47.98 47.23,48.03 | 47.23,48.03 47.43,48.33 47.43,51.53 47.28,51.68 v47.28,52.03 | v55.93,36.28 56.28,35.98 56.28,34.63 57.08,33.83 57.08,32.53 56.28,31.78 IC1.37 | v50.28,41.98 50.28,43.88 49.28,44.93 49.28,45.78 47.23,48.03
  Bottom 0.15: v9.08,31.78 9.63,31.78 9.88,32.03 11.13,32.03 12.03,31.13 v12.03,30.88 | v32.68,39.88 36.53,43.83 v36.93,43.83 | v47.28,52.03 48.28,53.28 X3.7 | v50.28,41.98 v55.93,36.28
SDA1  (via drill 0.25)
  Top 0.15: v9.58,33.63 9.18,33.03 9.18,32.58 8.83,32.28 7.38,32.28 IC3.8 | v29.93,46.58 31.63,44.73 35.78,44.73 36.88,45.88 37.33,46.38 v38.98,46.38 | v56.48,37.78 56.78,37.58 56.78,34.88 57.53,34.13 57.53,32.28 56.78,31.53 IC1.36
  Bottom 0.15: v9.58,33.63 14.48,33.63 27.58,46.58 v29.93,46.58 | v38.98,46.38 40.53,47.93 40.53,49.98 41.53,50.93 47.68,50.93 49.48,53.38 X3.8 50.18,53.98 50.68,54.53 62.13,54.53 62.53,54.18 62.53,46.23 61.63,45.33 58.33,45.33 56.48,43.58 v56.48,37.78
SDI2  (via drill 0.25)
  Top 0.15: 37.48,19.28 38.53,18.58 40.83,18.58 41.88,19.63 52.18,19.63 52.73,18.98 52.73,18.78 IC1.5 | 37.48,19.28 37.48,27.78 34.78,30.48 34.08,30.48 IC7.2 31.98,30.18 v30.68,29.78 | v25.98,18.58 27.13,18.58 28.13,19.28 37.48,19.28 | v28.68,34.23 28.38,34.28 27.98,34.28 IC8.8
  Bottom 0.15: v25.98,18.58 24.98,18.58 U$4.P$10 | v28.68,34.23 28.68,32.18 v30.68,29.78
SDMMC  (via drill 0.25)
  Top 0.15: v25.68,3.98 23.48,3.98 v23.33,4.08 | v25.18,16.08 25.18,26.48 v22.78,28.83 | v56.43,15.88 IC1.12
  Bottom 0.15: v56.43,15.88 56.43,8.88 52.58,4.88 46.58,4.88 46.43,5.08 45.73,5.08 44.53,3.88 42.88,3.88 42.78,3.78 27.13,3.78 26.93,3.98 v25.68,3.98 | v23.33,4.08 23.33,10.33 25.18,12.23 v25.18,16.08 | v22.78,28.83 22.78,32.58 23.38,33.18 U$4.P$4
SDO2  (via drill 0.25)
  Top 0.15: v26.28,32.78 26.78,32.78 IC7.5 28.88,33.18 31.38,33.18 32.48,34.28 33.08,34.28 IC8.1 35.18,34.78 v35.68,35.13 | v53.18,20.98 53.23,18.78 IC1.6
  Bottom 0.15: v26.28,32.78 24.98,31.48 U$4.P$5 | v53.18,20.98 53.18,22.13 52.18,23.13 52.18,24.48 51.48,25.33 51.48,29.08 50.63,29.88 49.08,29.88 48.18,30.78 42.98,36.23 36.58,36.23 v35.68,35.13
SDPOW  (via drill 0.25)
  Top 0.15: v25.78,14.98 25.23,14.98 24.28,15.93 24.28,18.78 21.78,21.58 21.78,26.58 R15.2 | v25.63,5.93 26.63,5.93 v27.13,5.53 | v43.43,4.48 45.98,4.48 v45.98,4.38 | v60.18,14.98 58.43,14.98 56.78,16.68 IC1.13
  Bottom 0.15: v25.63,5.93 25.63,6.23 25.78,6.38 v25.78,14.98 | v27.13,5.53 27.18,5.53 28.48,4.28 43.38,4.28 v43.43,4.48 | v45.98,4.38 51.28,4.38 52.08,3.58 53.23,3.58 53.73,4.08 60.13,10.53 v60.18,14.98
SENSBAT  (via drill 0.25)
  Top 0.15: v60.78,15.63 58.83,15.63 58.03,16.83 57.83,17.38 IC1.15 | v52.73,2.98 54.08,2.98 54.53,2.53 54.53,1.93 53.93,0.98 53.88,0.93 v53.73,0.93 | v48.73,3.73 v49.68,2.63 | v43.58,2.18 v45.33,3.73 | v20.28,2.18 18.48,4.08 12.93,4.08 12.53,4.48 R3.1 11.88,4.78 10.78,4.78 R7.2 9.98,5.08 9.98,10.68 9.23,11.43 v9.23,14.78 | v43.58,52.68 43.18,52.68 42.03,51.53 v38.38,51.53 | v30.33,47.33 v31.23,46.03
  Bottom 0.15: v60.78,15.63 60.78,10.18 53.83,3.18 53.63,2.98 v52.73,2.98 | v53.73,0.93 51.28,0.93 v49.68,2.63 | v45.33,3.73 v48.73,3.73 | v20.28,2.18 v43.58,2.18 | v43.58,52.68 46.28,52.68 46.98,53.38 X3.6 | v38.38,51.53 38.08,51.38 36.58,49.93 36.58,48.83 33.28,46.03 v31.23,46.03 | v30.33,47.33 22.58,47.33 12.58,37.28 6.83,37.28 6.38,37.78 5.73,37.78 2.88,35.13 2.88,21.03 v9.23,14.78
SI!INT  (via drill 0.25)
  Top 0.15: v3.53,32.83 4.08,32.78 IC3.18 | v3.53,29.33 3.58,28.88 D2.C
  Bottom 0.15: v3.53,29.33 v3.53,32.83
SI!RST  (via drill 0.25)
  Top 0.15: v7.18,30.08 6.58,30.68 6.58,30.88 IC3.5 | v13.73,27.68 16.48,30.48 v18.93,30.48 | v38.43,37.88 39.93,36.43 39.93,35.48 41.68,33.93 41.68,24.83 46.13,20.18 48.08,20.18 IC1.64
  Bottom 0.15: v7.18,30.08 7.33,30.08 9.78,27.68 v13.73,27.68 | v18.93,30.48 27.18,38.48 31.23,38.48 31.43,38.68 37.48,38.68 v38.43,37.88
SI!SEN  (via drill 0.25)
  Top 0.15: v8.13,30.88 7.48,30.88 IC3.6 | v15.38,28.28 v16.78,26.68 | v22.43,25.33 22.43,22.88 23.13,22.18 v24.33,22.18 | v29.38,16.58 29.73,15.93 31.28,15.93 32.93,17.58 41.23,17.58 42.28,18.63 v45.18,18.63 | v46.38,20.83 47.38,20.83 47.88,21.18 IC1.62
  Bottom 0.15: v8.13,30.88 8.28,30.88 8.13,30.73 10.63,28.28 v15.38,28.28 | v16.78,26.68 21.13,26.68 v22.43,25.33 | v24.33,22.18 25.43,22.18 25.73,21.88 25.73,20.23 v29.38,16.58 | v45.18,18.63 45.18,19.38 v46.38,20.83
SILOUT  (via drill 0.25)
  Top 0.15: C6.2 7.48,38.78 7.48,40.38 8.18,41.08 X6.2 | v12.18,37.88 14.13,37.88 C21.2
  Bottom 0.15: v12.18,37.88 8.78,41.38 X6.2
SIROUT
  Top 0.15: C7.1 8.53,38.78 10.38,40.58 11.98,40.58 12.63,41.28 X5.2 12.98,41.08 14.58,41.08 C20.1
U1CTS  (via drill 0.25)
  Top 0.15: v53.08,27.68 53.23,28.98 IC1.43 | v52.93,25.23 51.08,25.23 v50.48,24.63 | v51.48,12.23 51.48,9.78 53.18,8.08 53.33,7.98 IC14.39
  Bottom 0.15: v53.08,27.68 53.03,27.48 52.38,27.03 52.38,25.83 52.63,25.53 v52.93,25.23 | v50.48,24.63 50.23,24.38 50.23,23.23 50.58,22.88 50.58,22.68 50.98,22.28 50.98,16.38 50.58,15.98 50.58,15.08 50.93,14.73 51.48,14.03 v51.48,12.23
U1RTS  (via drill 0.25)
  Top 0.15: v49.68,9.23 49.68,7.98 51.03,6.63 52.33,6.63 52.43,6.53 53.23,6.53 IC14.42 | v55.88,21.23 55.88,23.18 v56.18,23.48 | v55.88,27.83 57.28,28.78 IC1.35
  Bottom 0.15: v49.68,9.23 50.58,9.58 52.73,11.68 52.73,16.33 56.28,19.93 56.28,20.88 v55.88,21.23 | v56.18,23.48 55.48,23.48 54.23,24.73 54.23,25.83 55.88,27.48 v55.88,27.83
U1RX  (via drill 0.25)
  Top 0.15: v51.18,7.43 51.73,7.03 53.33,7.03 IC14.41 | v61.68,28.18 59.33,30.78 58.08,30.78 57.73,30.43 IC1.34 | v64.88,22.78 66.13,21.78 66.13,18.08 65.58,17.68 X7.4
  Bottom 0.15: v51.18,7.43 51.33,7.43 51.58,7.68 51.58,8.73 54.28,11.43 54.28,16.13 55.63,17.43 64.83,17.43 X7.4 | v61.68,28.18 61.68,25.98 v64.88,22.78
U1TX  (via drill 0.25)
  Top 0.15: v52.63,4.18 49.08,7.98 49.08,9.78 49.38,10.08 49.78,10.08 52.28,7.58 53.33,7.53 IC14.40 | v60.53,16.53 62.48,16.53 63.43,17.43 63.43,18.33 64.93,19.73 X7.2 64.78,19.98 v63.78,20.63 | v58.48,26.83 58.43,28.98 IC1.33
  Bottom 0.15: v52.63,4.18 59.53,11.28 59.53,15.78 v60.53,16.53 | v58.48,26.83 58.38,26.58 63.78,20.98 v63.78,20.63
U2RX  (via drill 0.25)
  Top 0.15: v62.48,26.93 61.03,27.18 IC1.31
  Bottom 0.15: v62.48,26.93 64.78,24.68 X1.4
U2TX  (via drill 0.25)
  Top 0.15: v63.68,27.58 60.98,27.58 IC1.32
  Bottom 0.15: v63.68,27.58 64.38,27.58 64.78,27.18 X1.2
V+  (via drill 0.25)
  Top 0.15: 31.48,51.88 31.48,52.38 R28.2 | 31.48,51.88 31.48,50.98 IC11.9 | C51.1 31.48,53.48 31.48,52.98 R28.2 | 31.48,51.88 v31.28,51.88 | v40.58,19.83 40.58,20.38 41.63,21.38 41.63,23.23 41.13,23.63 41.13,33.48 v39.78,34.63 38.78,35.63 38.78,36.38 36.38,38.78 v36.38,39.98 | v36.53,41.63 34.08,41.63 29.23,46.48 29.23,51.08 30.53,52.48 31.13,52.48 R28.2
  Bottom 0.15: v31.28,51.88 31.28,53.18 31.98,53.88 33.58,53.88 C43.+ | v40.58,19.83 41.28,19.88 U$1.3 | v39.78,34.63 40.18,34.83 U$1.33 | v36.38,39.98 36.38,40.03 36.53,40.18 v36.53,41.63
VCCINT  (via drill 0.25)
  Top 0.15: IC14.18 62.23,6.03 62.33,5.98 62.83,5.53 63.78,5.53 64.08,5.83 64.08,8.18 63.33,8.93 62.18,8.93 IC14.24 61.13,9.08 61.13,11.18 60.78,11.28 59.88,11.28 59.83,11.23 | v52.33,5.48 53.33,5.53 IC14.44 | IC14.35 55.58,10.98 v55.58,11.48 55.78,11.38 58.88,11.38 | 59.83,11.23 59.68,11.38 58.88,11.38 | 59.83,11.23 59.98,11.08 59.98,10.98 IC14.26 | C3.2 62.18,42.28 62.18,41.58 C28.2 62.13,40.68 v62.13,40.08 | IC6.5 51.88,36.68 52.18,36.23 52.58,36.23 52.88,36.68 IC6.7 | 52.73,44.18 52.33,44.58 52.33,45.53 IC6.31 52.38,46.93 v52.63,47.28 | 52.73,44.18 53.23,44.08 53.48,43.98 55.93,43.98 56.33,44.38 56.43,44.38 IC6.24 | v45.58,49.23 45.28,48.98 45.13,48.68 43.73,48.68 42.83,49.28 41.58,49.28 IC10.5 | v51.88,43.43 51.88,43.53 53.38,42.03 53.38,40.73 51.88,39.23 51.88,37.58 IC6.5 | v53.03,44.13 52.73,44.18 | 58.88,11.38 v58.88,11.53 | v58.88,16.78 v58.98,18.03 | v51.73,35.33 51.73,35.48 51.88,35.63 51.88,36.48 IC6.5
  Bottom 0.15: v52.33,5.48 52.33,5.53 52.58,5.78 52.58,8.48 v55.58,11.48 | v45.58,49.23 50.23,49.23 v52.63,47.28 | v53.03,44.13 v51.88,43.43 51.98,43.38 54.28,41.08 54.28,39.83 54.73,39.23 54.73,38.13 55.68,37.18 56.78,37.18 57.08,37.53 57.08,38.68 58.33,40.08 v62.13,40.08 | v58.88,11.53 v58.88,16.78 | v58.98,18.03 58.88,18.88 58.08,19.68 58.08,20.38 56.58,21.83 54.53,21.83 52.73,23.73 52.73,24.48 51.93,25.43 51.93,29.63 51.18,30.33 49.33,30.33 48.68,30.98 48.68,31.48 49.18,31.98 50.68,31.98 51.73,33.03 v51.73,35.33
VCCIO  (via drill 0.25)
  Top 0.15: v63.73,12.43 63.73,13.23 IC12.5 | v65.88,9.93 66.08,9.58 66.13,9.48 66.13,4.23 65.53,3.58 62.18,3.58 IC14.13
  Bottom 0.15: v63.73,12.43 63.73,11.73 v65.88,9.93
VSDREQ  (via drill 0.25)
  Top 0.15: v54.18,32.08 53.38,32.98 53.38,36.68 IC6.8 | v57.23,26.98 58.08,26.23 59.38,26.23 IC1.29
  Bottom 0.15: v54.18,32.08 54.18,30.58 56.33,28.48 56.58,28.23 56.58,27.78 57.23,27.13 v57.23,26.98
VSGBUF  (via drill 0.25)
  Top 0.15: 8.28,50.88 IC13.4 | R22**.2 3.28,45.88 | R21.2 20.38,48.08 v19.13,49.38 19.13,49.83 20.48,51.48 23.58,51.48 24.13,50.93 24.13,50.73 29.18,45.18 v29.13,44.83 | v46.48,42.08 46.78,41.93 IC6.42 | v43.28,42.08 v45.28,41.78
  Top 0.305: 3.28,45.88 7.53,50.13 | 7.53,50.13 8.28,50.88 | 7.53,50.13 v7.58,49.38
  Bottom 0.15: v7.58,49.38 v19.13,49.38 | v45.28,41.78 v46.48,42.08 | v43.28,42.08 43.08,41.98 40.03,44.83 v29.13,44.83
VSLOUT  (via drill 0.25)
  Top 0.15: R14.2 21.28,45.98 21.88,45.98 R24.2 22.68,45.68 23.08,45.23 24.13,45.23 24.98,44.38 v28.28,44.38 | v43.58,40.58 43.83,40.58 43.98,40.48 46.28,40.48 46.73,39.93 47.63,39.93 IC6.46
  Bottom 0.15: v43.58,40.58 39.78,44.38 29.83,44.38 29.53,44.08 28.58,44.08 v28.28,44.38
VSROUT  (via drill 0.25)
  Top 0.15: R20.2 21.28,44.28 21.88,44.28 R23.2 22.68,43.88 22.98,43.58 v26.68,43.58 | v46.53,43.28 47.68,43.38 IC6.39 | v45.43,44.18 42.68,44.18 v42.83,44.08
  Bottom 0.15: v45.43,44.18 v46.53,43.28 | v42.83,44.08 41.48,44.08 40.13,45.38 31.58,45.38 31.38,45.23 29.63,45.23 29.43,45.48 28.43,45.48 v26.68,43.58
VSRX  (via drill 0.25)
  Top 0.15: R9.1 55.98,49.48 55.98,52.88 56.38,53.28 X2.4 | v54.73,47.88 54.83,47.68 IC6.26
  Bottom 0.15: v54.73,47.88 54.73,51.53 56.38,53.28 X2.4
VSSCLK  (via drill 0.25)
  Top 0.15: v57.38,31.13 62.08,35.78 62.08,37.18 65.98,40.93 65.98,49.08 65.18,49.78 63.28,49.78 61.98,48.33 61.98,46.53 61.43,45.93 60.23,45.93 59.58,45.23 54.23,45.23 53.88,45.68 IC6.28 | v56.28,26.98 v57.38,27.98 | v55.48,26.18 55.68,26.18 59.13,22.73 59.73,22.73 IC1.22
  Bottom 0.15: v57.38,27.98 v57.38,31.13 | v55.48,26.18 v56.28,26.98
VSSI/OLEDDB9  (via drill 0.25)
  Top 0.15: v53.83,44.78 53.38,45.68 IC6.29 | 44.08,31.28 44.08,31.18 44.13,31.13 44.13,31.03 44.08,30.98 43.58,30.53 v43.53,30.33 | 44.08,31.28 v46.78,33.98 | v57.28,22.23 59.68,22.23 IC1.21 | v53.58,25.78 53.23,25.88 50.73,25.88 v50.08,25.38 | 44.08,31.28 v46.33,29.18
  Bottom 0.15: v53.83,44.78 53.33,45.78 52.13,45.78 47.48,41.38 47.48,34.58 v46.78,33.98 | v43.53,30.33 42.28,30.38 U$1.24 | v53.58,25.78 53.58,24.68 55.63,22.48 55.88,22.23 v57.28,22.23 | v46.33,29.18 49.53,25.58 49.93,25.38 v50.08,25.38
VSSO  (via drill 0.25)
  Top 0.15: v52.93,44.98 52.88,45.68 IC6.30 | v53.78,28.18 53.78,27.08 v58.08,22.78 | v59.03,20.63 59.68,20.68 IC1.18
  Bottom 0.15: v52.93,44.98 52.08,45.03 49.73,42.88 49.73,39.38 54.88,34.38 54.88,33.88 54.48,33.53 53.73,33.53 53.23,33.03 53.23,32.13 53.78,31.58 v53.78,28.18 | v58.08,22.78 58.08,21.68 v59.03,20.63
VSTX  (via drill 0.25)
  Top 0.15: v53.88,48.13 53.88,47.68 54.38,47.18 IC6.27
  Bottom 0.15: v53.88,48.13 53.88,53.23 X2.2
VSXCS  (via drill 0.25)
  Top 0.15: v58.53,44.43 57.58,43.88 IC6.23 | v65.58,23.38 64.88,23.48 64.68,23.68 61.68,23.68 61.28,23.23 60.98,23.23 IC1.23
  Bottom 0.15: v58.53,44.43 59.28,44.43 65.98,38.08 66.13,23.78 v65.58,23.38
VSXRESET  (via drill 0.25)
  Top 0.15: 49.98,35.78 49.98,34.88 R5.1 | 49.98,35.78 50.88,36.68 IC6.3 | v59.03,30.18 59.03,27.18 59.38,26.78 59.48,26.73 IC1.30 | v54.23,34.13 v54.23,32.93 | 49.98,35.78 v49.18,36.58
  Bottom 0.15: v59.03,30.18 57.78,31.78 55.58,31.78 54.63,32.93 v54.23,32.93 | v54.23,34.13 54.28,34.28 51.98,36.58 v49.18,36.58

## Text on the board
tNames: techdesign.be | 048 | 048 | omniboard.be
bNames: techdesign.be | 048 | 048 | omniboard.be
